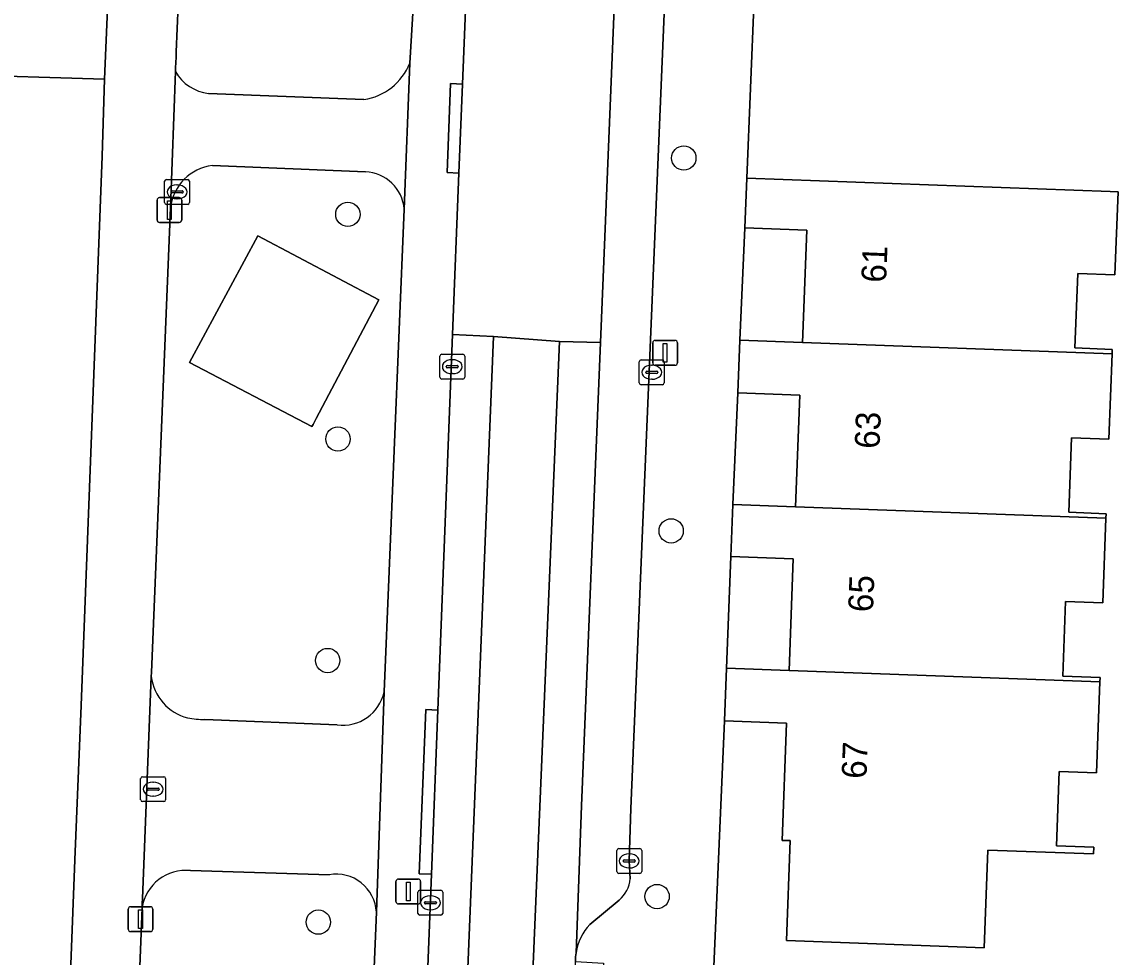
# Model space of a CAD drawing. Extents: x 160786 to 161429, y 386828 to 387485.
# Drawn here: x 161279.33 to 161323.4, y 387030.08 to 387067.7 of the extents above; entities that cross this region are included whole.
import ezdxf

# ---------------------------------------------------------------- set-up
doc = ezdxf.new("R2010")
doc.units = 0
for name, color, linetype in [('IMGEO_Boom', 7, 'Continuous'), ('IMGEO_Erf', 7, 'Continuous'), ('IMGEO_Groenvoorziening', 7, 'Continuous'), ('IMGEO_Kolk', 7, 'Continuous'), ('IMGEO_Lichtmast', 7, 'Continuous'), ('IMGEO_Muur', 7, 'Continuous'), ('IMGEO_Pand', 7, 'Continuous'), ('IMGEO_Pand_nummerreeks', 7, 'Continuous'), ('IMGEO_Parkeervlak_gesloten', 7, 'Continuous'), ('IMGEO_Rijbaan_lokaal_gesloten', 7, 'Continuous'), ('IMGEO_Terreindeel_gesloten', 7, 'Continuous'), ('IMGEO_Voetpad_open', 7, 'Continuous')]:
    doc.layers.add(name, color=color, linetype=linetype)

msp = doc.modelspace()

# ---------------------------------------------------------------- linework, layer by layer
at = {"layer": 'IMGEO_Boom'}
for centre in [(161305.936, 387062.221), (161292.429, 387059.955), (161292.03, 387050.917), (161305.428, 387047.221), (161291.619, 387042.007), (161304.862, 387032.513), (161291.241, 387031.484)]:
    msp.add_circle(centre, 0.489, dxfattribs=at)
at = {"layer": 'IMGEO_Erf'}
for points in [[(161308.913, 387072.289), (161308.47, 387061.416), (161323.076, 387060.875), (161323.396, 387060.863), (161323.272, 387057.523), (161321.772, 387057.578), (161321.662, 387054.58), (161323.161, 387054.525), (161323.154, 387054.345), (161323.027, 387050.912), (161321.527, 387050.967), (161321.417, 387047.969), (161322.916, 387047.914), (161322.909, 387047.734), (161322.783, 387044.326), (161321.283, 387044.381), (161321.173, 387041.383), (161322.672, 387041.328), (161322.665, 387041.148), (161322.529, 387037.493), (161321.03, 387037.548), (161320.919, 387034.55), (161322.418, 387034.495), (161322.408, 387034.225), (161318.154, 387034.383), (161318.009, 387030.456), (161310.059, 387030.751), (161310.208, 387034.761), (161309.896, 387034.772), (161310.071, 387039.491), (161307.574, 387039.583), (161307.145, 387029.702)], [(161270.474, 386995.066), (161279.6, 386994.71), (161279.893, 386994.699), (161280.357, 387005.827), (161280.607, 387011.897), (161281.457, 387033.987), (161281.713, 387040.195), (161282.55, 387062.294), (161282.648, 387065.39), (161276.481, 387065.585)]]:
    msp.add_lwpolyline(points, dxfattribs=at)
for points in [[(161308.193, 387054.899), (161310.709, 387054.805), (161310.876, 387059.319), (161308.395, 387059.411)], [(161310.596, 387052.681), (161308.114, 387052.774), (161307.903, 387048.288), (161310.429, 387048.195)], [(161307.653, 387041.703), (161310.166, 387041.61), (161310.332, 387046.093), (161307.825, 387046.186)]]:
    msp.add_lwpolyline(points, close=True, dxfattribs=at)
at = {"layer": 'IMGEO_Groenvoorziening'}
for points in [[(161295.396, 387073.867), (161292.398, 387073.991), (161292.18, 387068.099), (161285.604, 387068.369), (161285.531, 387066.49), (161285.522, 387066.274), (161285.513, 387066.061), (161285.505, 387065.853), (161285.499, 387065.7)], [(161294.915, 387066.036), (161295.396, 387073.867)], [(161286.828, 387064.821), (161293.076, 387064.572)], [(161293.138, 387061.663), (161286.982, 387061.919)], [(161285.305, 387060.233), (161284.534, 387041.522), (161284.528, 387041.367)], [(161293.887, 387040.743), (161294.697, 387060.166)], [(161286.683, 387039.634), (161292.003, 387039.422)], [(161291.685, 387033.391), (161286.103, 387033.554)], [(161284.157, 387032.058), (161283.451, 387014.153), (161283.413, 387012.864)], [(161292.771, 387012.758), (161293.577, 387031.886)]]:
    msp.add_lwpolyline(points, dxfattribs=at)
msp.add_lwpolyline([(161286.061, 387053.996), (161288.807, 387059.092), (161293.679, 387056.517), (161291.158, 387051.745), (161291.033, 387051.508), (161290.986, 387051.419)], close=True, dxfattribs=at)
for centre, radius, start, end in [((161292.725, 387066.901), 2.355, 278.5837, 338.4618), ((161287.024, 387066.561), 1.751, 209.4589, 263.5799), ((161287.21, 387060.015), 1.917, 96.8249, 173.4817), ((161293.071, 387060.033), 1.632, 4.6841, 87.6404), ((161286.486, 387041.603), 1.972, 186.8694, 255.2641), ((161292.236, 387041.093), 1.687, 262.0464, 348.0274), ((161286.801, 387044.934), 5.301, 261.1362, 268.7263), ((161285.907, 387031.795), 1.77, 83.6404, 171.4627), ((161291.961, 387031.797), 1.618, 3.1692, 99.8294)]:
    msp.add_arc(centre, radius, start, end, dxfattribs=at)
at = {"layer": 'IMGEO_Kolk'}
for p, q in [((161285.063, 387060.431), (161285.063, 387061.283)), ((161285.138, 387061.357), (161285.99, 387061.357)), ((161285.551, 387061.137), (161285.576, 387061.137)), ((161286.064, 387061.283), (161286.064, 387060.431)), ((161285.322, 387060.851), (161285.322, 387060.863)), ((161285.76, 387060.814), (161285.362, 387060.814)), ((161285.365, 387060.9), (161285.763, 387060.9)), ((161285.574, 387060.577), (161285.549, 387060.577)), ((161285.806, 387060.863), (161285.806, 387060.851)), ((161285.99, 387060.357), (161285.138, 387060.357)), ((161296.203, 387054.327), (161297.055, 387054.327)), ((161296.128, 387053.401), (161296.128, 387054.253)), ((161296.616, 387054.107), (161296.641, 387054.107)), ((161297.129, 387054.253), (161297.129, 387053.401)), ((161304.147, 387053.176), (161304.147, 387054.028)), ((161304.222, 387054.102), (161305.074, 387054.102)), ((161304.635, 387053.882), (161304.66, 387053.882)), ((161305.148, 387054.028), (161305.148, 387053.176)), ((161296.387, 387053.821), (161296.387, 387053.833)), ((161296.825, 387053.784), (161296.427, 387053.784)), ((161296.43, 387053.87), (161296.828, 387053.87)), ((161296.639, 387053.547), (161296.614, 387053.547)), ((161296.871, 387053.833), (161296.871, 387053.821)), ((161304.406, 387053.596), (161304.406, 387053.608)), ((161304.844, 387053.559), (161304.446, 387053.559)), ((161304.449, 387053.645), (161304.847, 387053.645)), ((161304.89, 387053.608), (161304.89, 387053.596)), ((161297.055, 387053.327), (161296.203, 387053.327)), ((161305.074, 387053.102), (161304.222, 387053.102)), ((161304.658, 387053.322), (161304.633, 387053.322)), ((161284.099, 387036.405), (161284.099, 387037.257)), ((161284.174, 387037.331), (161285.026, 387037.331)), ((161285.1, 387037.257), (161285.1, 387036.405)), ((161284.358, 387036.825), (161284.358, 387036.837)), ((161284.796, 387036.788), (161284.398, 387036.788)), ((161284.401, 387036.874), (161284.799, 387036.874)), ((161284.587, 387037.111), (161284.612, 387037.111)), ((161284.842, 387036.837), (161284.842, 387036.825)), ((161285.026, 387036.331), (161284.174, 387036.331)), ((161284.61, 387036.551), (161284.585, 387036.551)), ((161303.243, 387033.519), (161303.243, 387034.371)), ((161303.318, 387034.445), (161304.17, 387034.445)), ((161303.731, 387034.225), (161303.756, 387034.225)), ((161304.244, 387034.371), (161304.244, 387033.519)), ((161303.502, 387033.939), (161303.502, 387033.951)), ((161303.94, 387033.902), (161303.542, 387033.902)), ((161303.545, 387033.988), (161303.943, 387033.988)), ((161303.754, 387033.665), (161303.729, 387033.665)), ((161303.986, 387033.951), (161303.986, 387033.939)), ((161304.17, 387033.445), (161303.318, 387033.445)), ((161295.322, 387032.763), (161296.174, 387032.763)), ((161295.247, 387031.837), (161295.247, 387032.689)), ((161295.549, 387032.306), (161295.947, 387032.306)), ((161295.735, 387032.543), (161295.76, 387032.543)), ((161296.248, 387032.689), (161296.248, 387031.837)), ((161295.506, 387032.257), (161295.506, 387032.269)), ((161295.944, 387032.22), (161295.546, 387032.22)), ((161295.758, 387031.983), (161295.733, 387031.983)), ((161295.99, 387032.269), (161295.99, 387032.257)), ((161296.174, 387031.763), (161295.322, 387031.763))]:
    msp.add_line(p, q, dxfattribs=at)
for points in [[(161285.063, 387060.431), (161285.063, 387061.283)], [(161285.138, 387061.357), (161285.99, 387061.357)], [(161286.064, 387061.283), (161286.064, 387060.431)], [(161285.99, 387060.357), (161285.138, 387060.357)], [(161296.203, 387054.327), (161297.055, 387054.327)], [(161296.128, 387053.401), (161296.128, 387054.253)], [(161297.129, 387054.253), (161297.129, 387053.401)], [(161304.147, 387053.176), (161304.147, 387054.028)], [(161304.222, 387054.102), (161305.074, 387054.102)], [(161305.148, 387054.028), (161305.148, 387053.176)], [(161297.055, 387053.327), (161296.203, 387053.327)], [(161305.074, 387053.102), (161304.222, 387053.102)], [(161284.099, 387036.405), (161284.099, 387037.257)], [(161284.174, 387037.331), (161285.026, 387037.331)], [(161285.1, 387037.257), (161285.1, 387036.405)], [(161285.026, 387036.331), (161284.174, 387036.331)], [(161303.243, 387033.519), (161303.243, 387034.371)], [(161303.318, 387034.445), (161304.17, 387034.445)], [(161304.244, 387034.371), (161304.244, 387033.519)], [(161304.17, 387033.445), (161303.318, 387033.445)], [(161295.322, 387032.763), (161296.174, 387032.763)], [(161295.247, 387031.837), (161295.247, 387032.689)], [(161296.248, 387032.689), (161296.248, 387031.837)], [(161296.174, 387031.763), (161295.322, 387031.763)]]:
    msp.add_lwpolyline(points, dxfattribs=at)
for centre, radius, start, end in [((161285.14, 387061.281), 0.0765, 91.552, 178.448), ((161285.14, 387061.281), 0.0765, 91.552, 178.448), ((161285.988, 387061.281), 0.0765, 1.552, 88.448), ((161285.988, 387061.281), 0.0765, 1.552, 88.448), ((161285.362, 387060.86), 0.0403, 85.8775, 175.7526), ((161285.359, 387060.85), 0.0366, 178.938, 274.7102), ((161285.763, 387060.857), 0.043, 264.8664, 352.4533), ((161285.767, 387060.862), 0.0386, 1.7309, 96.639), ((161285.14, 387060.433), 0.0765, 181.552, 268.448), ((161285.14, 387060.433), 0.0765, 181.552, 268.448), ((161285.988, 387060.433), 0.0765, 271.552, 358.448), ((161285.988, 387060.433), 0.0765, 271.552, 358.448), ((161296.205, 387054.251), 0.0765, 91.552, 178.448), ((161296.205, 387054.251), 0.0765, 91.552, 178.448), ((161297.053, 387054.251), 0.0765, 1.552, 88.448), ((161297.053, 387054.251), 0.0765, 1.552, 88.448), ((161304.224, 387054.026), 0.0765, 91.552, 178.448), ((161304.224, 387054.026), 0.0765, 91.552, 178.448), ((161305.072, 387054.026), 0.0765, 1.552, 88.448), ((161305.072, 387054.026), 0.0765, 1.552, 88.448), ((161296.427, 387053.83), 0.0403, 85.8775, 175.7526), ((161296.424, 387053.82), 0.0366, 178.938, 274.7102), ((161296.828, 387053.827), 0.043, 264.8664, 352.4533), ((161296.832, 387053.832), 0.0386, 1.7309, 96.639), ((161304.446, 387053.605), 0.0403, 85.8775, 175.7526), ((161304.443, 387053.595), 0.0366, 178.938, 274.7102), ((161304.847, 387053.602), 0.043, 264.8664, 352.4533), ((161304.851, 387053.607), 0.0386, 1.7309, 96.639), ((161296.205, 387053.403), 0.0765, 181.552, 268.448), ((161296.205, 387053.403), 0.0765, 181.552, 268.448), ((161297.053, 387053.403), 0.0765, 271.552, 358.448), ((161297.053, 387053.403), 0.0765, 271.552, 358.448), ((161304.224, 387053.178), 0.0765, 181.552, 268.448), ((161304.224, 387053.178), 0.0765, 181.552, 268.448), ((161305.072, 387053.178), 0.0765, 271.552, 358.448), ((161305.072, 387053.178), 0.0765, 271.552, 358.448), ((161284.176, 387037.255), 0.0765, 91.552, 178.448), ((161284.176, 387037.255), 0.0765, 91.552, 178.448), ((161285.024, 387037.255), 0.0765, 1.552, 88.448), ((161285.024, 387037.255), 0.0765, 1.552, 88.448), ((161284.398, 387036.834), 0.0403, 85.8775, 175.7526), ((161284.395, 387036.824), 0.0366, 178.938, 274.7102), ((161284.799, 387036.831), 0.043, 264.8664, 352.4533), ((161284.803, 387036.836), 0.0386, 1.7309, 96.639), ((161284.176, 387036.407), 0.0765, 181.552, 268.448), ((161284.176, 387036.407), 0.0765, 181.552, 268.448), ((161285.024, 387036.407), 0.0765, 271.552, 358.448), ((161285.024, 387036.407), 0.0765, 271.552, 358.448), ((161303.32, 387034.369), 0.0765, 91.552, 178.448), ((161303.32, 387034.369), 0.0765, 91.552, 178.448), ((161304.168, 387034.369), 0.0765, 1.552, 88.448), ((161304.168, 387034.369), 0.0765, 1.552, 88.448), ((161303.542, 387033.948), 0.0403, 85.8775, 175.7526), ((161303.539, 387033.938), 0.0366, 178.938, 274.7102), ((161303.943, 387033.945), 0.043, 264.8664, 352.4533), ((161303.947, 387033.95), 0.0386, 1.7309, 96.639), ((161303.32, 387033.521), 0.0765, 181.552, 268.448), ((161303.32, 387033.521), 0.0765, 181.552, 268.448), ((161304.168, 387033.521), 0.0765, 271.552, 358.448), ((161304.168, 387033.521), 0.0765, 271.552, 358.448), ((161295.324, 387032.687), 0.0765, 91.552, 178.448), ((161295.324, 387032.687), 0.0765, 91.552, 178.448), ((161296.172, 387032.687), 0.0765, 1.552, 88.448), ((161296.172, 387032.687), 0.0765, 1.552, 88.448), ((161295.546, 387032.266), 0.0403, 85.8775, 175.7526), ((161295.951, 387032.268), 0.0386, 1.7309, 96.639), ((161295.543, 387032.256), 0.0366, 178.938, 274.7102), ((161295.947, 387032.263), 0.043, 264.8664, 352.4533), ((161295.324, 387031.839), 0.0765, 181.552, 268.448), ((161295.324, 387031.839), 0.0765, 181.552, 268.448), ((161296.172, 387031.839), 0.0765, 271.552, 358.448), ((161296.172, 387031.839), 0.0765, 271.552, 358.448)]:
    msp.add_arc(centre, radius, start, end, dxfattribs=at)
for centre, major_axis, ratio, start_param, end_param in [((161285.55, 387060.857), (-0.387, 0.002), 0.722429, 4.712389, 7.853982), ((161285.575, 387060.857), (-0.39, 0.002), 0.717154, 1.570796, 4.712389), ((161296.615, 387053.827), (-0.387, 0.002), 0.722429, 4.712389, 7.853982), ((161296.64, 387053.827), (-0.39, 0.002), 0.717154, 1.570796, 4.712389), ((161304.634, 387053.602), (-0.387, 0.002), 0.722429, 4.712389, 7.853982), ((161304.659, 387053.602), (-0.39, 0.002), 0.717154, 1.570796, 4.712389), ((161284.586, 387036.831), (-0.387, 0.002), 0.722429, 4.712389, 7.853982), ((161284.611, 387036.831), (-0.39, 0.002), 0.717154, 1.570796, 4.712389), ((161303.73, 387033.945), (-0.387, 0.002), 0.722429, 4.712389, 7.853982), ((161303.755, 387033.945), (-0.39, 0.002), 0.717154, 1.570796, 4.712389), ((161295.734, 387032.263), (-0.387, 0.002), 0.722429, 4.712389, 7.853982), ((161295.759, 387032.263), (-0.39, 0.002), 0.717154, 1.570796, 4.712389)]:
    msp.add_ellipse(centre, major_axis=major_axis, ratio=ratio, start_param=start_param, end_param=end_param, dxfattribs=at)
at = {"layer": 'IMGEO_Lichtmast'}
for p, q in [((161284.759, 387059.727), (161284.759, 387060.527)), ((161284.759, 387060.527), (161284.759, 387059.727)), ((161284.859, 387060.627), (161285.649, 387060.627)), ((161285.649, 387060.627), (161284.859, 387060.627)), ((161285.749, 387060.527), (161285.749, 387059.727)), ((161285.749, 387059.727), (161285.749, 387060.527)), ((161285.649, 387059.627), (161284.859, 387059.627)), ((161284.859, 387059.627), (161285.649, 387059.627)), ((161304.689, 387053.986), (161304.689, 387054.786)), ((161304.689, 387054.786), (161304.689, 387053.986)), ((161304.789, 387054.886), (161305.579, 387054.886)), ((161305.579, 387054.886), (161304.789, 387054.886)), ((161305.679, 387054.786), (161305.679, 387053.986)), ((161305.679, 387053.986), (161305.679, 387054.786)), ((161305.579, 387053.886), (161304.789, 387053.886)), ((161304.789, 387053.886), (161305.579, 387053.886)), ((161294.464, 387033.217), (161295.254, 387033.217)), ((161295.254, 387033.217), (161294.464, 387033.217)), ((161294.364, 387032.317), (161294.364, 387033.117)), ((161294.364, 387033.117), (161294.364, 387032.317)), ((161295.354, 387033.117), (161295.354, 387032.317)), ((161295.354, 387032.317), (161295.354, 387033.117)), ((161283.599, 387031.201), (161283.599, 387032.001)), ((161283.599, 387032.001), (161283.599, 387031.201)), ((161283.699, 387032.101), (161284.489, 387032.101)), ((161284.489, 387032.101), (161283.699, 387032.101)), ((161284.589, 387032.001), (161284.589, 387031.201)), ((161284.589, 387031.201), (161284.589, 387032.001)), ((161295.254, 387032.217), (161294.464, 387032.217)), ((161294.464, 387032.217), (161295.254, 387032.217)), ((161284.489, 387031.101), (161283.699, 387031.101)), ((161283.699, 387031.101), (161284.489, 387031.101))]:
    msp.add_line(p, q, dxfattribs=at)
for points in [[(161285.179, 387060.502), (161285.329, 387060.502), (161285.329, 387059.752), (161285.179, 387059.752), (161285.179, 387060.502)], [(161305.109, 387054.761), (161305.259, 387054.761), (161305.259, 387054.011), (161305.109, 387054.011), (161305.109, 387054.761)], [(161294.784, 387033.092), (161294.934, 387033.092), (161294.934, 387032.342), (161294.784, 387032.342), (161294.784, 387033.092)], [(161284.019, 387031.976), (161284.169, 387031.976), (161284.169, 387031.226), (161284.019, 387031.226), (161284.019, 387031.976)]]:
    msp.add_lwpolyline(points, dxfattribs=at)
for centre, start, end in [((161284.859, 387060.527), 90, 180), ((161284.859, 387060.527), 90, 180), ((161285.649, 387060.527), 0, 90), ((161285.649, 387060.527), 360, 90), ((161284.859, 387059.727), 180, 270), ((161284.859, 387059.727), 180, 270), ((161285.649, 387059.727), 270, 0), ((161285.649, 387059.727), 270, 0), ((161304.789, 387054.786), 90, 180), ((161304.789, 387054.786), 90, 180), ((161305.579, 387054.786), 0, 90), ((161305.579, 387054.786), 360, 90), ((161304.789, 387053.986), 180, 270), ((161304.789, 387053.986), 180, 270), ((161305.579, 387053.986), 270, 0), ((161305.579, 387053.986), 270, 0), ((161294.464, 387033.117), 90, 180), ((161294.464, 387033.117), 90, 180), ((161295.254, 387033.117), 0, 90), ((161295.254, 387033.117), 360, 90), ((161294.464, 387032.317), 180, 270), ((161294.464, 387032.317), 180, 270), ((161295.254, 387032.317), 270, 0), ((161295.254, 387032.317), 270, 0), ((161283.699, 387032.001), 90, 180), ((161283.699, 387032.001), 90, 180), ((161284.489, 387032.001), 0, 90), ((161284.489, 387032.001), 360, 90), ((161283.699, 387031.201), 180, 270), ((161283.699, 387031.201), 180, 270), ((161284.489, 387031.201), 270, 0), ((161284.489, 387031.201), 270, 0)]:
    msp.add_arc(centre, 0.1, start, end, dxfattribs=at)
at = {"layer": 'IMGEO_Muur'}
for points in [[(161282.55, 387062.294), (161281.713, 387040.195)], [(161281.457, 387033.987), (161280.607, 387011.897)]]:
    msp.add_lwpolyline(points, dxfattribs=at)
at = {"layer": 'IMGEO_Pand'}
for points in [[(161323.396, 387060.863), (161323.076, 387060.875), (161308.47, 387061.416), (161308.395, 387059.411), (161310.876, 387059.319), (161310.709, 387054.805), (161323.154, 387054.345), (161323.161, 387054.525), (161321.662, 387054.58), (161321.772, 387057.578), (161323.272, 387057.523)], [(161323.154, 387054.345), (161310.709, 387054.805), (161308.193, 387054.899), (161308.114, 387052.774), (161310.596, 387052.681), (161310.429, 387048.195), (161322.909, 387047.734), (161322.916, 387047.914), (161321.417, 387047.969), (161321.527, 387050.967), (161323.027, 387050.912)], [(161322.909, 387047.734), (161310.429, 387048.195), (161307.903, 387048.288), (161307.825, 387046.186), (161310.332, 387046.093), (161310.166, 387041.61), (161322.665, 387041.148), (161322.672, 387041.328), (161321.173, 387041.383), (161321.283, 387044.381), (161322.783, 387044.326)], [(161322.529, 387037.493), (161322.665, 387041.148), (161310.166, 387041.61), (161307.653, 387041.703), (161307.574, 387039.583), (161310.071, 387039.491), (161309.896, 387034.772), (161310.208, 387034.761), (161310.059, 387030.751), (161318.009, 387030.456), (161318.154, 387034.383), (161322.408, 387034.225), (161322.418, 387034.495), (161320.919, 387034.55), (161321.03, 387037.548)]]:
    msp.add_lwpolyline(points, close=True, dxfattribs=at)
at = {"layer": 'IMGEO_Parkeervlak_gesloten'}
for points in [[(161304.257, 387095.993), (161304.004, 387090.321), (161303.31, 387072.416), (161303.22, 387070.236), (161302.759, 387059.05), (161302.586, 387054.794), (161301.823, 387036.16), (161301.604, 387030.255)], [(161303.783, 387033.226), (161303.744, 387033.945), (161303.813, 387036.061), (161303.844, 387037), (161306.037, 387089.142)], [(161302.16, 387031.393), (161303.334, 387032.373)]]:
    msp.add_lwpolyline(points, dxfattribs=at)
for centre, radius, start, end in [((161302.498, 387033.358), 1.292, 310.3352, 354.1422), ((161303.759, 387029.907), 2.183, 137.095, 170.8269)]:
    msp.add_arc(centre, radius, start, end, dxfattribs=at)
at = {"layer": 'IMGEO_Rijbaan_lokaal_gesloten'}
msp.add_lwpolyline([(161303.22, 387070.236), (161301.538, 387070.326), (161298.846, 387070.446), (161297.253, 387070.5), (161297.036, 387065.197), (161296.896, 387061.618), (161296.641, 387055.12), (161298.285, 387055.038), (161300.938, 387054.844), (161302.586, 387054.794), (161302.759, 387059.05)], close=True, dxfattribs=at)
for points in [[(161295.615, 386998.468), (161296.227, 387004.228), (161298.285, 387055.038), (161296.641, 387055.12), (161296.047, 387040.014), (161295.788, 387033.414), (161294.936, 387011.744), (161294.673, 387005.041), (161294.475, 387000), (161293.996, 386989.734), (161293.806, 386983.797), (161290.641, 386907.552)], [(161294.661, 386902.681), (161299.353, 387017.413), (161300.938, 387054.844), (161298.285, 387055.038), (161296.227, 387004.228), (161295.615, 386998.468)], [(161298.691, 386958.606), (161298.922, 386964.506), (161300.177, 386996.031), (161300.266, 386998.149), (161301.03, 387016.276), (161301.348, 387024.011), (161301.576, 387029.9), (161301.584, 387030.091), (161301.604, 387030.255), (161301.823, 387036.16), (161302.586, 387054.794), (161300.938, 387054.844), (161299.353, 387017.413), (161294.661, 386902.681)]]:
    msp.add_lwpolyline(points, dxfattribs=at)
at = {"layer": 'IMGEO_Terreindeel_gesloten'}
msp.add_lwpolyline([(161293.679, 387056.517), (161288.807, 387059.092), (161286.061, 387053.996), (161290.986, 387051.419), (161291.033, 387051.508), (161291.158, 387051.745)], close=True, dxfattribs=at)
at = {"layer": 'IMGEO_Voetpad_open'}
for points in [[(161296.641, 387055.12), (161296.896, 387061.618), (161296.419, 387061.633), (161296.552, 387065.213), (161297.036, 387065.197), (161297.253, 387070.5), (161298.203, 387093.746), (161298.327, 387096.773), (161297.126, 387096.827), (161296.267, 387096.866), (161296.129, 387093.823), (161294.38, 387093.888)], [(161285.499, 387065.7), (161285.505, 387065.853), (161285.513, 387066.061), (161285.522, 387066.274), (161285.531, 387066.49), (161285.604, 387068.369), (161286.113, 387081.436), (161286.571, 387092.573), (161286.579, 387092.677), (161286.588, 387092.78), (161286.6, 387092.883), (161286.614, 387092.984), (161286.632, 387093.085)], [(161306.177, 387092.765), (161306.037, 387089.142), (161303.844, 387037), (161303.813, 387036.061), (161303.744, 387033.945), (161303.783, 387033.226)], [(161296.068, 387091.985), (161295.396, 387073.867), (161294.915, 387066.036), (161294.697, 387060.166), (161293.887, 387040.743), (161293.577, 387031.886), (161292.771, 387012.758), (161292.459, 387003.6), (161291.803, 386991.13)], [(161304.643, 386967.566), (161304.735, 386969.75), (161304.905, 386974.209), (161304.998, 386976.414), (161305.162, 386980.793), (161305.254, 386982.981), (161305.433, 386987.42), (161305.522, 386989.524), (161305.942, 387000), (161305.991, 387001.219), (161306.231, 387007.346), (161306.763, 387021.339), (161306.892, 387024.216), (161307.145, 387029.702), (161307.574, 387039.583), (161307.653, 387041.703), (161307.825, 387046.186), (161307.903, 387048.288), (161308.114, 387052.774), (161308.193, 387054.899), (161308.395, 387059.411), (161308.47, 387061.416), (161308.913, 387072.289)], [(161237.976, 387066.877), (161241.482, 387066.822), (161241.242, 387061.076), (161242.837, 387060.993), (161243.124, 387066.674), (161251.749, 387066.28), (161253.087, 387066.217), (161253.1, 387066.636), (161262.744, 387066.176), (161275.241, 387065.69), (161276.481, 387065.585), (161282.648, 387065.39), (161282.865, 387070.428), (161282.861, 387070.505)], [(161282.865, 387070.428), (161282.648, 387065.39), (161282.55, 387062.294), (161281.713, 387040.195), (161281.457, 387033.987), (161280.607, 387011.897)], [(161294.697, 387060.166), (161294.915, 387066.036)], [(161283.451, 387014.153), (161284.157, 387032.058), (161284.164, 387032.247), (161284.172, 387032.433), (161284.528, 387041.367), (161284.534, 387041.522), (161285.305, 387060.233), (161285.499, 387065.7)], [(161285.499, 387065.7), (161285.305, 387060.233)], [(161293.076, 387064.572), (161286.828, 387064.821)], [(161286.982, 387061.919), (161293.138, 387061.663)], [(161290.499, 386989.812), (161293.996, 386989.734), (161294.475, 387000), (161294.673, 387005.041), (161294.166, 387005.058), (161294.419, 387011.762), (161294.936, 387011.744), (161295.788, 387033.414), (161295.297, 387033.432), (161295.571, 387040.031), (161296.047, 387040.014), (161296.641, 387055.12)], [(161284.528, 387041.367), (161284.172, 387032.433), (161284.164, 387032.247), (161284.157, 387032.058)], [(161293.577, 387031.886), (161293.887, 387040.743)], [(161292.003, 387039.422), (161286.683, 387039.634)], [(161286.103, 387033.554), (161291.685, 387033.391)], [(161303.334, 387032.373), (161302.16, 387031.393)], [(161301.604, 387030.255), (161301.584, 387030.091), (161301.576, 387029.9), (161302.708, 387029.836), (161302.503, 387023.985), (161301.348, 387024.011)]]:
    msp.add_lwpolyline(points, dxfattribs=at)
for points in [[(161296.896, 387061.618), (161297.036, 387065.197), (161296.552, 387065.213), (161296.419, 387061.633)], [(161295.788, 387033.414), (161296.047, 387040.014), (161295.571, 387040.031), (161295.297, 387033.432)]]:
    msp.add_lwpolyline(points, close=True, dxfattribs=at)
for centre, radius, start, end in [((161292.725, 387066.901), 2.355, 278.5837, 338.4618), ((161287.024, 387066.561), 1.751, 209.4589, 263.5799), ((161287.21, 387060.015), 1.917, 96.8249, 173.4817), ((161293.071, 387060.033), 1.632, 4.6841, 87.6404), ((161286.486, 387041.603), 1.972, 186.8694, 255.2641), ((161292.236, 387041.093), 1.687, 262.0464, 348.0274), ((161286.801, 387044.934), 5.301, 261.1362, 268.7263), ((161285.907, 387031.795), 1.77, 83.6404, 171.4627), ((161291.961, 387031.797), 1.618, 3.1692, 99.8294), ((161302.498, 387033.358), 1.292, 310.3352, 354.1422), ((161303.759, 387029.907), 2.183, 137.095, 170.8269)]:
    msp.add_arc(centre, radius, start, end, dxfattribs=at)

# ---------------------------------------------------------------- texts
at = {"layer": 'IMGEO_Pand_nummerreeks'}
for s, rotation, p in [('61', 87.7198, (161314.068, 387057.194)), ('63', 87.7198, (161313.802, 387050.511)), ('65', 87.7198, (161313.54, 387043.939)), ('67', 87.737, (161313.276, 387037.237))]:
    msp.add_text(s, height=1, rotation=rotation, dxfattribs=at).set_placement(p)

doc.saveas('drawing.dxf')
